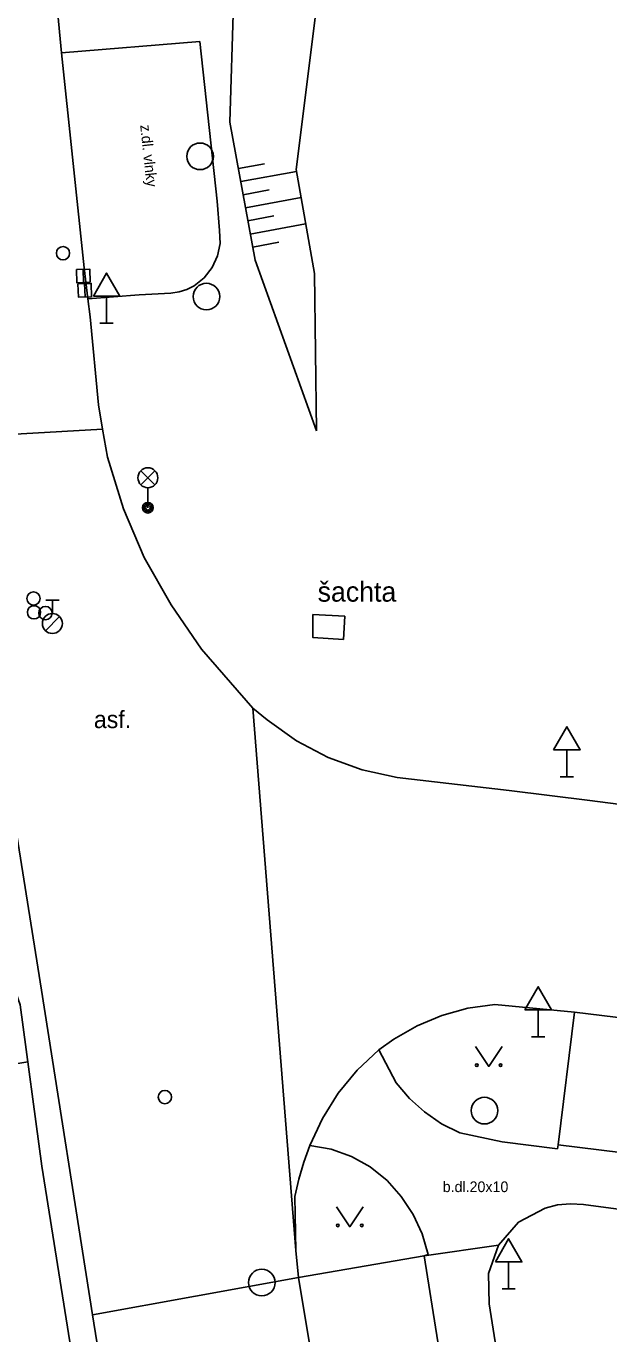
# Model space of a CAD drawing. Extents: x -598932 to -598196, y -1162207 to -1161504.
# Drawn here: x -598793.37 to -598771.48, y -1162206.96 to -1162157.54 of the extents above; entities that cross this region are included whole.
import ezdxf

# ---------------------------------------------------------------- set-up
doc = ezdxf.new("R2010")
doc.units = 0
for name, color, linetype in [('Level 27', 7, 'Continuous'), ('Level 28', 7, 'Continuous'), ('Level 33', 7, 'Continuous'), ('Level 34', 7, 'Continuous'), ('Level 36', 7, 'Continuous'), ('specificka linie pasportu komunikaci', 7, 'Continuous'), ('TM - chodniky - VP', 7, 'Continuous'), ('TM - dolni hrana svahu', 7, 'Continuous'), ('TM - horni hrana svahu', 7, 'Continuous'), ('TM - komunikace - VP', 7, 'Continuous'), ('TM - plot dreveny_ kovovy - VP', 7, 'Continuous'), ('TM - popis povrchu', 7, 'Continuous'), ('TM - poznamka', 7, 'Continuous'), ('TM - rozhrani mezi zpev. plochami mezi sebou - VP', 7, 'Continuous'), ('TM - rozhrani ploch obecne - VP', 7, 'Continuous'), ('TM - srafovani', 7, 'Continuous')]:
    doc.layers.add(name, color=color, linetype=linetype)

msp = doc.modelspace()

# ---------------------------------------------------------------- linework, layer by layer
at = {"layer": 'Level 27'}
for p, q in [((-598791.237, -1162166.67), (-598791.223, -1162167.17)), ((-598791.177, -1162167.21), (-598791.163, -1162167.71))]:
    msp.add_line(p, q, dxfattribs=at)
for points in [[(-598791.487, -1162166.677), (-598791.473, -1162167.177), (-598790.973, -1162167.163), (-598790.987, -1162166.663)], [(-598791.427, -1162167.217), (-598791.413, -1162167.717), (-598790.913, -1162167.703), (-598790.927, -1162167.203)]]:
    msp.add_lwpolyline(points, close=True, dxfattribs=at)
for centre in [(-598786.84, -1162162.43), (-598786.6, -1162167.7), (-598776.15, -1162198.28), (-598784.52, -1162204.74)]:
    msp.add_circle(centre, 0.5, dxfattribs=at)
at = {"layer": 'Level 28'}
for p, q in [((-598792.64, -1162179.105), (-598792.14, -1162179.105)), ((-598792.39, -1162179.605), (-598792.39, -1162179.105)), ((-598792.648, -1162180.252), (-598792.118, -1162179.722))]:
    msp.add_line(p, q, dxfattribs=at)
for centre, radius in [((-598791.99, -1162166.07), 0.25), ((-598793.1, -1162179.04), 0.25), ((-598793.08, -1162179.56), 0.25), ((-598792.65, -1162179.59), 0.25), ((-598792.39, -1162179.98), 0.375), ((-598788.16, -1162197.77), 0.25)]:
    msp.add_circle(centre, radius, dxfattribs=at)
at = {"layer": 'Level 33'}
for p, q in [((-598789.065, -1162174.77), (-598788.535, -1162174.24)), ((-598789.065, -1162174.24), (-598788.535, -1162174.77)), ((-598788.8, -1162174.88), (-598788.8, -1162175.63))]:
    msp.add_line(p, q, dxfattribs=at)
for centre, radius in [((-598788.8, -1162174.505), 0.375), ((-598788.8, -1162175.63), 0.2), ((-598788.8, -1162175.63), 0.145), ((-598788.8, -1162175.63), 0.0876)]:
    msp.add_circle(centre, radius, dxfattribs=at)
at = {"layer": 'Level 34'}
for p, q in [((-598790.35, -1162167.682), (-598790.35, -1162168.7)), ((-598790.6, -1162168.7), (-598790.1, -1162168.7)), ((-598773.05, -1162184.722), (-598773.05, -1162185.74)), ((-598773.3, -1162185.74), (-598772.8, -1162185.74)), ((-598774.13, -1162194.492), (-598774.13, -1162195.51)), ((-598774.38, -1162195.51), (-598773.88, -1162195.51)), ((-598775.24, -1162203.962), (-598775.24, -1162204.98)), ((-598775.49, -1162204.98), (-598774.99, -1162204.98))]:
    msp.add_line(p, q, dxfattribs=at)
for points in [[(-598790.85, -1162167.682), (-598789.85, -1162167.682), (-598790.35, -1162166.816)], [(-598773.55, -1162184.722), (-598772.55, -1162184.722), (-598773.05, -1162183.856)], [(-598774.63, -1162194.492), (-598773.63, -1162194.492), (-598774.13, -1162193.626)], [(-598775.74, -1162203.962), (-598774.74, -1162203.962), (-598775.24, -1162203.096)]]:
    msp.add_lwpolyline(points, close=True, dxfattribs=at)
at = {"layer": 'Level 36'}
for points in [[(-598776.49, -1162195.87), (-598775.99, -1162196.62), (-598775.49, -1162195.87)], [(-598781.71, -1162201.89), (-598781.21, -1162202.64), (-598780.71, -1162201.89)]]:
    msp.add_lwpolyline(points, dxfattribs=at)
for centre in [(-598776.44, -1162196.57), (-598775.541, -1162196.57), (-598781.66, -1162202.59), (-598780.761, -1162202.59)]:
    msp.add_circle(centre, 0.05, dxfattribs=at)
at = {"layer": 'specificka linie pasportu komunikaci'}
for points in [[(-598790.5, -1162172.68), (-598796.63, -1162173.03)], [(-598783.24, -1162203.53), (-598784.86, -1162183.16)], [(-598775.62, -1162203.33), (-598778.41, -1162203.74)], [(-598790.88, -1162205.95), (-598783.14, -1162204.55)]]:
    msp.add_lwpolyline(points, dxfattribs=at)
at = {"layer": 'TM - chodniky - VP'}
for points in [[(-598779.47, -1162197.23), (-598780.12, -1162196)], [(-598778.4, -1162198.33), (-598778.97, -1162197.82), (-598779.47, -1162197.23)], [(-598777.77, -1162198.77), (-598778.4, -1162198.33)], [(-598777.08, -1162199.12), (-598777.77, -1162198.77)], [(-598773.4, -1162199.71), (-598775.48, -1162199.45), (-598777.08, -1162199.12)], [(-598782.71, -1162199.59), (-598781.91, -1162199.73), (-598781.15, -1162200), (-598780.44, -1162200.39), (-598779.81, -1162200.9)], [(-598773.4, -1162199.71), (-598773.38, -1162199.57)], [(-598779.81, -1162200.9), (-598779.28, -1162201.5), (-598778.83, -1162202.18), (-598778.49, -1162202.91), (-598778.26, -1162203.68)], [(-598773.4, -1162201.82), (-598773.87, -1162201.94)], [(-598773.4, -1162201.82), (-598772.91, -1162201.78), (-598772.43, -1162201.81)], [(-598763.45, -1162202.95), (-598768.41, -1162202.34), (-598772.43, -1162201.81)], [(-598775.97, -1162205.54), (-598776, -1162204.4), (-598775.62, -1162203.33), (-598774.87, -1162202.47), (-598773.87, -1162201.94)], [(-598778.41, -1162203.74), (-598778.26, -1162203.68)], [(-598775.97, -1162205.54), (-598775.743, -1162206.96)]]:
    msp.add_lwpolyline(points, dxfattribs=at)
at = {"layer": 'TM - dolni hrana svahu'}
for points in [[(-598782.17, -1162151.7), (-598782.35, -1162155.91), (-598783.23, -1162162.93), (-598782.54, -1162166.83), (-598782.46, -1162172.74)], [(-598791.733, -1162206.96), (-598792.79, -1162200.37), (-598793.6, -1162194.3), (-598796.4, -1162186.37)]]:
    msp.add_lwpolyline(points, dxfattribs=at)
at = {"layer": 'TM - horni hrana svahu'}
msp.add_lwpolyline([(-598782.46, -1162172.74), (-598784.77, -1162166.33), (-598785.72, -1162161.14)], dxfattribs=at)
at = {"layer": 'TM - komunikace - VP'}
for points in [[(-598792.05, -1162158.54), (-598794.01, -1162137.8), (-598793.97, -1162137.55), (-598793.44, -1162134.37), (-598792.44, -1162131.65), (-598790.89, -1162129), (-598788.65, -1162126.55), (-598786.61, -1162125.41)], [(-598792.05, -1162158.54), (-598786.85, -1162158.12)], [(-598786.85, -1162158.12), (-598786.2, -1162164.11)], [(-598786.2, -1162164.11), (-598786.11, -1162165.21), (-598786.08, -1162165.7)], [(-598786.08, -1162165.7), (-598786.18, -1162166.17)], [(-598786.18, -1162166.17), (-598786.39, -1162166.61), (-598786.68, -1162166.99), (-598787.06, -1162167.29)], [(-598787.34, -1162167.43), (-598787.06, -1162167.29)], [(-598791.06, -1162167.78), (-598789.13, -1162167.63)], [(-598791.06, -1162167.78), (-598790.97, -1162168.46)], [(-598789.13, -1162167.63), (-598787.94, -1162167.57)], [(-598787.34, -1162167.43), (-598787.63, -1162167.52), (-598787.94, -1162167.57)], [(-598790.97, -1162168.46), (-598790.66, -1162171.76)], [(-598790.66, -1162171.76), (-598790.5, -1162172.68), (-598790.32, -1162173.73)], [(-598788.94, -1162177.5), (-598789.72, -1162175.67), (-598790.32, -1162173.73)], [(-598788.94, -1162177.5), (-598787.93, -1162179.28)], [(-598787.93, -1162179.28), (-598786.79, -1162180.94)], [(-598786.79, -1162180.94), (-598784.86, -1162183.16)], [(-598784.86, -1162183.16), (-598784.32, -1162183.6)], [(-598779.43, -1162185.76), (-598780.75, -1162185.48), (-598782.02, -1162185.02), (-598783.22, -1162184.39), (-598784.32, -1162183.6)], [(-598779.43, -1162185.76), (-598775.22, -1162186.25)], [(-598775.22, -1162186.25), (-598772.19, -1162186.63)], [(-598772.19, -1162186.63), (-598771.12, -1162186.77), (-598769.83, -1162186.86), (-598743.36, -1162190.15)], [(-598790.719, -1162206.96), (-598790.88, -1162205.95), (-598792.8, -1162193.76), (-598793.72, -1162187.93)], [(-598779.56, -1162195.6), (-598778.68, -1162195.09), (-598777.75, -1162194.7), (-598776.77, -1162194.43), (-598775.76, -1162194.29)], [(-598772.77, -1162194.58), (-598775.76, -1162194.29)], [(-598773.38, -1162199.57), (-598772.77, -1162194.58)], [(-598780.12, -1162196), (-598779.56, -1162195.6)], [(-598782.71, -1162199.59), (-598782.24, -1162198.57), (-598781.65, -1162197.63), (-598780.94, -1162196.76), (-598780.12, -1162196)], [(-598783.13, -1162200.86), (-598782.94, -1162200.22), (-598782.71, -1162199.59)], [(-598773.38, -1162199.57), (-598743.34, -1162203.26)], [(-598783.28, -1162201.51), (-598783.13, -1162200.86)], [(-598783.24, -1162203.53), (-598783.28, -1162201.51)], [(-598783.14, -1162204.55), (-598783.24, -1162203.53)], [(-598783.14, -1162204.55), (-598778.41, -1162203.74)], [(-598777.906, -1162206.96), (-598778.41, -1162203.74)]]:
    msp.add_lwpolyline(points, dxfattribs=at)
at = {"layer": 'TM - plot dreveny_ kovovy - VP'}
msp.add_lwpolyline([(-598785.72, -1162161.14), (-598785.45, -1162152.22), (-598785.56, -1162151.24), (-598788.18, -1162151.29), (-598788.31, -1162144.11), (-598786.61, -1162125.41)], dxfattribs=at)
at = {"layer": 'TM - rozhrani mezi zpev. plochami mezi sebou - VP'}
for points in [[(-598791.06, -1162167.78), (-598791.19, -1162166.62), (-598792.05, -1162158.54)], [(-598772.77, -1162194.58), (-598762.79, -1162195.8)], [(-598783.14, -1162204.55), (-598782.743, -1162206.96)]]:
    msp.add_lwpolyline(points, dxfattribs=at)
at = {"layer": 'TM - rozhrani ploch obecne - VP'}
msp.add_lwpolyline([(-598782.6, -1162179.64), (-598781.4, -1162179.71), (-598781.45, -1162180.58), (-598782.6, -1162180.51), (-598782.6, -1162179.64)], dxfattribs=at)
at = {"layer": 'TM - srafovani'}
for points in [[(-598785.4, -1162162.89), (-598784.42, -1162162.71)], [(-598785.31, -1162163.38), (-598783.22, -1162163)], [(-598785.22, -1162163.87), (-598784.24, -1162163.69)], [(-598785.13, -1162164.36), (-598783.04, -1162163.98)], [(-598785.04, -1162164.85), (-598784.06, -1162164.67)], [(-598784.95, -1162165.35), (-598782.87, -1162164.97)], [(-598784.86, -1162165.84), (-598783.88, -1162165.66)], [(-598795.7, -1162196.85), (-598793.31, -1162196.45)]]:
    msp.add_lwpolyline(points, dxfattribs=at)

# ---------------------------------------------------------------- texts
at = {"layer": 'TM - popis povrchu'}
msp.add_text('z.dl. vlnky', height=0.4, rotation=276.0754, dxfattribs=at).set_placement((-598789.09, -1162161.26))
for s, height, p in [('asf.', 0.65, (-598790.83, -1162183.91)), ('b.dl.20x10', 0.4, (-598777.72, -1162201.34))]:
    msp.add_text(s, height=height, dxfattribs=at).set_placement(p)
at = {"layer": 'TM - poznamka'}
msp.add_text('šachta', height=0.75, dxfattribs=at).set_placement((-598782.42, -1162179.16))

doc.saveas('drawing.dxf')
